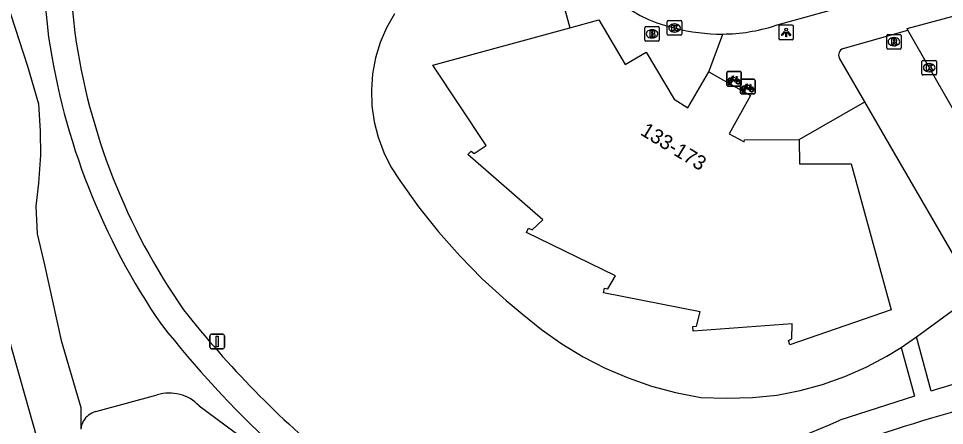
# Model space of a CAD drawing. Extents: x 159053 to 160041, y 380450 to 381422.
# Drawn here: x 159173.9 to 159237.4, y 380777.8 to 380805.8 of the extents above; entities that cross this region are included whole.
import ezdxf

# ---------------------------------------------------------------- set-up
doc = ezdxf.new("R2010")
doc.units = 0
for name, color, linetype in [('IMGEO_Brandkraan', 7, 'Continuous'), ('IMGEO_Fietsenrek', 7, 'Continuous'), ('IMGEO_Groenvoorziening', 7, 'Continuous'), ('IMGEO_Kolk', 7, 'Continuous'), ('IMGEO_Lichtpunt', 7, 'Continuous'), ('IMGEO_Pand', 7, 'Continuous'), ('IMGEO_Pand_nummerreeks', 7, 'Continuous'), ('IMGEO_Parkeervlak_open', 7, 'Continuous'), ('IMGEO_Rijbaan_lokaal_open', 7, 'Continuous'), ('IMGEO_Rioolput', 7, 'Continuous'), ('IMGEO_Verkeersbordpaal', 7, 'Continuous'), ('IMGEO_Voetpad_open', 7, 'Continuous'), ('IMGEO_Waterloop', 7, 'Continuous')]:
    doc.layers.add(name, color=color, linetype=linetype)

msp = doc.modelspace()

# ---------------------------------------------------------------- linework, layer by layer
at = {"layer": 'IMGEO_Brandkraan'}
for p, q in [((159216.878, 380804.302), (159216.878, 380805.154)), ((159216.953, 380805.228), (159217.805, 380805.228)), ((159217.366, 380805.008), (159217.391, 380805.008)), ((159217.879, 380805.154), (159217.879, 380804.302)), ((159217.805, 380804.228), (159216.953, 380804.228)), ((159217.389, 380804.448), (159217.364, 380804.448))]:
    msp.add_line(p, q, dxfattribs=at)
for points in [[(159216.878, 380804.302), (159216.878, 380805.154)], [(159216.953, 380805.228), (159217.805, 380805.228)], [(159217.226, 380804.928), (159217.226, 380804.528), (159217.439, 380804.528)], [(159217.457, 380804.928), (159217.226, 380804.928)], [(159217.405, 380804.847), (159217.351, 380804.847), (159217.351, 380804.771)], [(159217.351, 380804.771), (159217.404, 380804.771)], [(159217.879, 380805.154), (159217.879, 380804.302)], [(159217.805, 380804.228), (159216.953, 380804.228)], [(159217.413, 380804.695), (159217.351, 380804.695), (159217.351, 380804.614)], [(159217.351, 380804.614), (159217.413, 380804.614)]]:
    msp.add_lwpolyline(points, dxfattribs=at)
for centre, radius, start, end in [((159216.955, 380805.152), 0.0765, 91.55205, 178.44795), ((159216.955, 380805.152), 0.0765, 91.55205, 178.44795), ((159217.406, 380804.809), 0.0379, 267.82845, 90.93552), ((159217.461, 380804.783), 0.145, 59.4692, 91.53667), ((159217.486, 380804.83), 0.0922, 285.51372, 58.15012), ((159217.491, 380804.638), 0.105, 301.31148, 78.98903), ((159217.803, 380805.152), 0.0765, 1.55205, 88.44795), ((159217.803, 380805.152), 0.0765, 1.55205, 88.44795), ((159216.955, 380804.304), 0.0765, 181.55205, 268.44795), ((159216.955, 380804.304), 0.0765, 181.55205, 268.44795), ((159217.414, 380804.654), 0.0404, 269.87594, 90.50774), ((159217.445, 380804.779), 0.251, 268.66757, 293.53466), ((159217.803, 380804.304), 0.0765, 271.55205, 358.44795), ((159217.803, 380804.304), 0.0765, 271.55205, 358.44795)]:
    msp.add_arc(centre, radius, start, end, dxfattribs=at)
for centre, major_axis, ratio, start_param, end_param in [((159217.365, 380804.728), (-0.387, 0.002), 0.722429, 4.712389, 7.853982), ((159217.39, 380804.728), (-0.39, 0.002), 0.717154, 1.570796, 4.712389)]:
    msp.add_ellipse(centre, major_axis=major_axis, ratio=ratio, start_param=start_param, end_param=end_param, dxfattribs=at)
at = {"layer": 'IMGEO_Fietsenrek'}
for p, q in [((159222.506, 380801.224), (159222.506, 380802.065)), ((159222.506, 380802.065), (159222.506, 380801.224)), ((159222.581, 380802.149), (159223.422, 380802.149)), ((159223.422, 380802.149), (159222.581, 380802.149)), ((159223.193, 380801.698), (159223.229, 380801.603)), ((159223.506, 380802.074), (159223.506, 380801.233)), ((159223.506, 380801.233), (159223.506, 380802.074)), ((159223.524, 380801.608), (159224.365, 380801.608)), ((159224.365, 380801.608), (159223.524, 380801.608)), ((159223.431, 380801.149), (159222.59, 380801.149)), ((159222.59, 380801.149), (159223.431, 380801.149)), ((159222.633, 380801.233), (159222.672, 380801.393)), ((159222.667, 380801.233), (159222.633, 380801.233)), ((159222.702, 380801.381), (159222.667, 380801.233)), ((159222.744, 380801.405), (159222.743, 380801.409)), ((159222.785, 380801.233), (159222.751, 380801.375)), ((159222.775, 380801.416), (159222.776, 380801.409)), ((159222.783, 380801.379), (159222.818, 380801.233)), ((159222.818, 380801.233), (159222.785, 380801.233)), ((159223.449, 380800.683), (159223.449, 380801.524)), ((159223.449, 380801.524), (159223.449, 380800.683)), ((159224.136, 380801.157), (159224.172, 380801.062)), ((159224.449, 380801.533), (159224.449, 380800.692)), ((159224.449, 380800.692), (159224.449, 380801.533)), ((159224.374, 380800.608), (159223.533, 380800.608)), ((159223.533, 380800.608), (159224.374, 380800.608)), ((159223.576, 380800.692), (159223.615, 380800.852)), ((159223.61, 380800.692), (159223.576, 380800.692)), ((159223.645, 380800.84), (159223.61, 380800.692)), ((159223.687, 380800.864), (159223.686, 380800.868)), ((159223.728, 380800.692), (159223.694, 380800.834)), ((159223.718, 380800.875), (159223.719, 380800.868)), ((159223.726, 380800.838), (159223.761, 380800.692)), ((159223.761, 380800.692), (159223.728, 380800.692))]:
    msp.add_line(p, q, dxfattribs=at)
for points in [[(159222.84, 380801.623), (159222.788, 380801.533), (159222.748, 380801.508), (159222.749, 380801.555), (159222.804, 380801.649)], [(159222.819, 380801.675), (159222.914, 380801.839), (159223, 380801.825), (159223.002, 380801.816), (159222.946, 380801.805), (159222.919, 380801.76), (159223.175, 380801.719)], [(159223.115, 380801.431), (159223.065, 380801.431), (159222.874, 380801.682), (159222.855, 380801.65)], [(159223.162, 380801.694), (159222.905, 380801.735), (159222.888, 380801.706), (159223.055, 380801.486), (159223.162, 380801.694)], [(159223.21, 380801.596), (159223.18, 380801.673), (159223.071, 380801.455), (159223.114, 380801.455)], [(159223.144, 380801.455), (159223.264, 380801.454), (159223.22, 380801.568)], [(159223.24, 380801.575), (159223.295, 380801.43), (159223.145, 380801.43)], [(159223.175, 380801.719), (159223.2, 380801.768), (159223.194, 380801.772), (159223.171, 380801.776), (159223.159, 380801.783), (159223.158, 380801.786), (159223.16, 380801.791), (159223.255, 380801.776), (159223.257, 380801.766), (159223.247, 380801.753), (159223.235, 380801.747), (159223.221, 380801.753), (159223.193, 380801.698)], [(159223.783, 380801.082), (159223.731, 380800.992), (159223.691, 380800.967), (159223.692, 380801.014), (159223.747, 380801.108)], [(159223.762, 380801.134), (159223.857, 380801.298), (159223.943, 380801.284), (159223.945, 380801.275), (159223.889, 380801.264), (159223.862, 380801.219), (159224.118, 380801.178)], [(159224.058, 380800.89), (159224.008, 380800.89), (159223.817, 380801.141), (159223.798, 380801.109)], [(159224.105, 380801.153), (159223.848, 380801.194), (159223.831, 380801.165), (159223.998, 380800.945), (159224.105, 380801.153)], [(159224.153, 380801.055), (159224.123, 380801.132), (159224.014, 380800.914), (159224.057, 380800.914)], [(159224.087, 380800.914), (159224.207, 380800.913), (159224.163, 380801.027)], [(159224.183, 380801.034), (159224.238, 380800.889), (159224.088, 380800.889)], [(159224.118, 380801.178), (159224.143, 380801.227), (159224.137, 380801.231), (159224.114, 380801.235), (159224.102, 380801.242), (159224.101, 380801.245), (159224.103, 380801.25), (159224.198, 380801.235), (159224.2, 380801.225), (159224.19, 380801.212), (159224.178, 380801.206), (159224.164, 380801.212), (159224.136, 380801.157)]]:
    msp.add_lwpolyline(points, dxfattribs=at)
for centre, radius, start, end in [((159222.584, 380802.071), 0.0779, 92.4484, 184.28452), ((159222.584, 380802.071), 0.0779, 92.4484, 184.28452), ((159222.746, 380801.534), 0.159, 62.67661, 242.13685), ((159222.746, 380801.534), 0.129, 63.31916, 238.90302), ((159222.746, 380801.534), 0.129, 283.60429, 43.43025), ((159222.746, 380801.534), 0.159, 283.5766, 46.60424), ((159223.273, 380801.45), 0.159, 113.3408, 178.32165), ((159223.273, 380801.45), 0.159, 187.0065, 105.77075), ((159223.273, 380801.45), 0.129, 113.92302, 177.95563), ((159223.273, 380801.45), 0.129, 188.67146, 104.58832), ((159223.428, 380802.071), 0.0779, 2.4484, 94.28452), ((159223.428, 380802.071), 0.0779, 2.4484, 94.28452), ((159223.527, 380801.53), 0.0779, 92.4484, 184.28452), ((159223.527, 380801.53), 0.0779, 92.4484, 184.28452), ((159224.371, 380801.53), 0.0779, 2.4484, 94.28452), ((159224.371, 380801.53), 0.0779, 2.4484, 94.28452), ((159222.584, 380801.227), 0.0779, 182.4484, 274.28452), ((159222.584, 380801.227), 0.0779, 182.4484, 274.28452), ((159222.726, 380801.405), 0.0499, 12.8025, 158.69338), ((159222.746, 380801.534), 0.159, 253.99666, 271.78671), ((159222.726, 380801.405), 0.0174, 12.8025, 163.45023), ((159222.746, 380801.534), 0.129, 253.41502, 269.02044), ((159223.428, 380801.227), 0.0779, 272.4484, 4.28452), ((159223.428, 380801.227), 0.0779, 272.4484, 4.28452), ((159223.689, 380800.993), 0.159, 62.67661, 242.13685), ((159223.689, 380800.993), 0.129, 63.31916, 238.90302), ((159223.689, 380800.993), 0.129, 283.60429, 43.43025), ((159223.689, 380800.993), 0.159, 283.5766, 46.60424), ((159224.216, 380800.909), 0.159, 113.3408, 178.32165), ((159224.216, 380800.909), 0.159, 187.0065, 105.77075), ((159224.216, 380800.909), 0.129, 113.92302, 177.95563), ((159224.216, 380800.909), 0.129, 188.67146, 104.58832), ((159223.527, 380800.686), 0.0779, 182.4484, 274.28452), ((159223.527, 380800.686), 0.0779, 182.4484, 274.28452), ((159223.669, 380800.864), 0.0499, 12.8025, 158.69338), ((159223.689, 380800.993), 0.159, 253.99666, 271.78671), ((159223.669, 380800.864), 0.0174, 12.8025, 163.45023), ((159223.689, 380800.993), 0.129, 253.41502, 269.02044), ((159224.371, 380800.686), 0.0779, 272.4484, 4.28452), ((159224.371, 380800.686), 0.0779, 272.4484, 4.28452)]:
    msp.add_arc(centre, radius, start, end, dxfattribs=at)
at = {"layer": 'IMGEO_Groenvoorziening'}
for points in [[(159157.361, 380852.49), (159157.5, 380851.935), (159158.238, 380851.91), (159159.044, 380848.136), (159163.047, 380833.48), (159167.797, 380815.145), (159168.307, 380814.08), (159168.71, 380813.63), (159169.403, 380812.854), (159170.582, 380811.629), (159171.589, 380810.256), (159172.467, 380808.688), (159173.399, 380806.044), (159174.529, 380802.504), (159175.289, 380799.933), (159175.411, 380798.052), (159175.434, 380796.406), (159175.295, 380794.475), (159175.114, 380792.902), (159175.195, 380791.012), (159175.709, 380788.864), (159176.846, 380783.679), (159178.187, 380779.088), (159178.194, 380777.607)], [(159199.714, 380806.111), (159199.173, 380805.15), (159198.739, 380804.135), (159198.417, 380803.08), (159198.213, 380801.995), (159198.127, 380800.895), (159198.16, 380799.792), (159198.314, 380798.7), (159198.585, 380797.63), (159198.97, 380796.596), (159199.466, 380795.611), (159200.083, 380794.66), (159201.356, 380792.861), (159202.725, 380791.133), (159204.186, 380789.483), (159205.735, 380787.915), (159207.367, 380786.433), (159208.479, 380785.511), (159209.8, 380784.431), (159211.193, 380783.447), (159212.652, 380782.563), (159214.169, 380781.784), (159215.738, 380781.113), (159217.35, 380780.554), (159218.997, 380780.11), (159220.72, 380779.775), (159222.499, 380779.715), (159224.278, 380779.774), (159225.949, 380779.94), (159227.532, 380780.245), (159229.086, 380780.667), (159230.603, 380781.203), (159232.077, 380781.85), (159233.498, 380782.606), (159234.471, 380783.205)], [(159235.534, 380783.935), (159239.534, 380786.855)]]:
    msp.add_lwpolyline(points, dxfattribs=at)
at = {"layer": 'IMGEO_Kolk'}
for p, q in [((159218.424, 380804.709), (159218.424, 380805.561)), ((159218.499, 380805.635), (159219.351, 380805.635)), ((159218.912, 380805.415), (159218.937, 380805.415)), ((159219.425, 380805.561), (159219.425, 380804.709)), ((159218.935, 380804.855), (159218.91, 380804.855)), ((159219.351, 380804.635), (159218.499, 380804.635)), ((159235.897, 380801.98), (159235.897, 380802.832)), ((159235.972, 380802.906), (159236.824, 380802.906)), ((159236.898, 380802.832), (159236.898, 380801.98)), ((159236.385, 380802.686), (159236.41, 380802.686)), ((159236.824, 380801.906), (159235.972, 380801.906)), ((159236.408, 380802.126), (159236.383, 380802.126))]:
    msp.add_line(p, q, dxfattribs=at)
for points in [[(159218.424, 380804.709), (159218.424, 380805.561)], [(159218.499, 380805.635), (159219.351, 380805.635)], [(159219.425, 380805.561), (159219.425, 380804.709)], [(159218.745, 380805.335), (159218.868, 380805.335), (159218.868, 380805.184), (159218.998, 380805.335), (159219.162, 380805.335), (159219.016, 380805.184), (159219.169, 380804.935), (159219.017, 380804.935), (159218.932, 380805.099), (159218.868, 380805.032), (159218.868, 380804.935), (159218.745, 380804.935), (159218.745, 380805.335)], [(159219.351, 380804.635), (159218.499, 380804.635)], [(159235.897, 380801.98), (159235.897, 380802.832)], [(159235.972, 380802.906), (159236.824, 380802.906)], [(159236.898, 380802.832), (159236.898, 380801.98)], [(159236.218, 380802.606), (159236.341, 380802.606), (159236.341, 380802.455), (159236.471, 380802.606), (159236.635, 380802.606), (159236.489, 380802.455), (159236.642, 380802.206), (159236.49, 380802.206), (159236.405, 380802.37), (159236.341, 380802.303), (159236.341, 380802.206), (159236.218, 380802.206), (159236.218, 380802.606)], [(159236.824, 380801.906), (159235.972, 380801.906)]]:
    msp.add_lwpolyline(points, dxfattribs=at)
for centre, start, end in [((159218.501, 380805.559), 91.55205, 178.44795), ((159218.501, 380805.559), 91.55205, 178.44795), ((159219.349, 380805.559), 1.55205, 88.44795), ((159219.349, 380805.559), 1.55205, 88.44795), ((159218.501, 380804.711), 181.55205, 268.44795), ((159218.501, 380804.711), 181.55205, 268.44795), ((159219.349, 380804.711), 271.55205, 358.44795), ((159219.349, 380804.711), 271.55205, 358.44795), ((159235.974, 380802.83), 91.55205, 178.44795), ((159235.974, 380802.83), 91.55205, 178.44795), ((159236.822, 380802.83), 1.55205, 88.44795), ((159236.822, 380802.83), 1.55205, 88.44795), ((159235.974, 380801.982), 181.55205, 268.44795), ((159235.974, 380801.982), 181.55205, 268.44795), ((159236.822, 380801.982), 271.55205, 358.44795), ((159236.822, 380801.982), 271.55205, 358.44795)]:
    msp.add_arc(centre, 0.0765, start, end, dxfattribs=at)
for centre, major_axis, ratio, start_param, end_param in [((159218.911, 380805.135), (-0.387, 0.002), 0.722429, 4.712389, 7.853982), ((159218.936, 380805.135), (-0.39, 0.002), 0.717154, 1.570796, 4.712389), ((159236.384, 380802.406), (-0.387, 0.002), 0.722429, 4.712389, 7.853982), ((159236.409, 380802.406), (-0.39, 0.002), 0.717154, 1.570796, 4.712389)]:
    msp.add_ellipse(centre, major_axis=major_axis, ratio=ratio, start_param=start_param, end_param=end_param, dxfattribs=at)
at = {"layer": 'IMGEO_Lichtpunt'}
for p, q in [((159226.083, 380805.232), (159226.083, 380804.425)), ((159226.083, 380805.232), (159226.083, 380804.425)), ((159226.985, 380805.327), (159226.177, 380805.327)), ((159226.985, 380805.327), (159226.177, 380805.327)), ((159227.079, 380804.425), (159227.079, 380805.232)), ((159227.079, 380804.425), (159227.079, 380805.232)), ((159226.177, 380804.331), (159226.985, 380804.331)), ((159226.177, 380804.331), (159226.985, 380804.331))]:
    msp.add_line(p, q, dxfattribs=at)
for points in [[(159226.457, 380804.896), (159226.496, 380804.868), (159226.308, 380804.606), (159226.27, 380804.633), (159226.457, 380804.896)], [(159226.559, 380804.848), (159226.606, 380804.848), (159226.606, 380804.526), (159226.559, 380804.526), (159226.559, 380804.848)], [(159226.669, 380804.868), (159226.707, 380804.895), (159226.894, 380804.633), (159226.855, 380804.605), (159226.669, 380804.868)]]:
    msp.add_lwpolyline(points, dxfattribs=at)
msp.add_circle((159226.582, 380805.03), 0.0994, dxfattribs=at)
for centre, start, end in [((159226.177, 380805.232), 90, 180), ((159226.177, 380805.232), 90, 180), ((159226.985, 380805.232), 0, 90), ((159226.985, 380805.232), 0, 90), ((159226.177, 380804.425), 180, 270), ((159226.177, 380804.425), 180, 270), ((159226.985, 380804.425), 270, 0), ((159226.985, 380804.425), 270, 360)]:
    msp.add_arc(centre, 0.0946, start, end, dxfattribs=at)
at = {"layer": 'IMGEO_Pand'}
for points in [[(159211.745, 380805.145), (159213.733, 380805.694), (159215.531, 380802.628), (159216.973, 380803.467), (159218.889, 380800.241), (159219.838, 380799.655), (159221.267, 380802.133)], [(159227.479, 380797.488), (159227.498, 380795.798), (159231.043, 380795.813), (159233.78, 380785.791), (159226.843, 380783.387), (159226.748, 380783.688), (159226.977, 380783.797), (159226.987, 380784.819), (159220.196, 380784.331), (159220.178, 380784.645), (159220.435, 380784.659), (159220.677, 380785.65), (159214.062, 380786.958), (159214.118, 380787.272), (159214.355, 380787.231), (159214.864, 380788.117), (159208.762, 380791.103), (159208.905, 380791.387), (159209.165, 380791.267), (159209.891, 380791.973), (159204.744, 380796.453), (159204.968, 380796.686), (159205.181, 380796.525), (159206.007, 380797.068), (159202.339, 380802.574), (159211.745, 380805.145)], [(159221.267, 380802.133), (159224.143, 380800.501), (159222.679, 380797.864), (159223.697, 380797.317), (159223.726, 380797.455), (159227.479, 380797.488)]]:
    msp.add_lwpolyline(points, dxfattribs=at)
at = {"layer": 'IMGEO_Parkeervlak_open'}
msp.add_lwpolyline([(159238.879, 380788.148), (159234.015, 380796.548), (159231.975, 380800.065)], dxfattribs=at)
at = {"layer": 'IMGEO_Rijbaan_lokaal_open'}
for points in [[(159263.275, 380815.492), (159254.307, 380813.067), (159229.759, 380806.373), (159225.787, 380805.28)], [(159234.929, 380804.973), (159234.89, 380805.091), (159249.357, 380809.009), (159249.391, 380808.875)], [(159243.944, 380789.247), (159234.929, 380804.973)]]:
    msp.add_lwpolyline(points, dxfattribs=at)
for centre, radius, start, end in [((159220.896, 380814.173), 9.251, 195.99591, 257.67011), ((159222.105, 380816.98), 12.264, 254.95066, 270.58198), ((159222.115, 380816.943), 12.227, 270.54111, 287.47858)]:
    msp.add_arc(centre, radius, start, end, dxfattribs=at)
at = {"layer": 'IMGEO_Rioolput'}
for p, q in [((159233.478, 380803.763), (159233.478, 380804.615)), ((159233.553, 380804.689), (159234.405, 380804.689)), ((159233.966, 380804.469), (159233.991, 380804.469)), ((159234.479, 380804.615), (159234.479, 380803.763)), ((159234.405, 380803.689), (159233.553, 380803.689)), ((159233.989, 380803.909), (159233.964, 380803.909))]:
    msp.add_line(p, q, dxfattribs=at)
for points in [[(159233.478, 380803.763), (159233.478, 380804.615)], [(159233.553, 380804.689), (159234.405, 380804.689)], [(159234.067, 380804.387), (159233.815, 380804.389), (159233.815, 380803.989)], [(159233.815, 380803.989), (159233.939, 380803.989), (159233.939, 380804.151), (159233.95, 380804.151)], [(159233.993, 380804.308), (159233.939, 380804.308), (159233.939, 380804.227)], [(159233.939, 380804.227), (159233.991, 380804.227)], [(159233.997, 380804.122), (159234.068, 380803.989), (159234.208, 380803.989), (159234.143, 380804.115)], [(159234.479, 380804.615), (159234.479, 380803.763)], [(159234.405, 380803.689), (159233.553, 380803.689)]]:
    msp.add_lwpolyline(points, dxfattribs=at)
for centre, radius, start, end in [((159233.555, 380804.613), 0.0765, 91.55205, 178.44795), ((159233.555, 380804.613), 0.0765, 91.55205, 178.44795), ((159233.949, 380804.098), 0.0533, 26.02933, 88.69889), ((159233.975, 380804.416), 0.19, 274.7715, 282.96867), ((159233.999, 380804.212), 0.0964, 77.00612, 93.18647), ((159234.013, 380804.269), 0.0378, 276.66336, 79.67722), ((159234.066, 380804.277), 0.109, 350.36119, 89.41601), ((159234.064, 380804.277), 0.112, 277.58423, 350.98172), ((159234.048, 380804.062), 0.108, 29.51342, 73.79051), ((159234.403, 380804.613), 0.0765, 1.55205, 88.44795), ((159234.403, 380804.613), 0.0765, 1.55205, 88.44795), ((159233.555, 380803.765), 0.0765, 181.55205, 268.44795), ((159233.555, 380803.765), 0.0765, 181.55205, 268.44795), ((159234.403, 380803.765), 0.0765, 271.55205, 358.44795), ((159234.403, 380803.765), 0.0765, 271.55205, 358.44795)]:
    msp.add_arc(centre, radius, start, end, dxfattribs=at)
for centre, major_axis, ratio, start_param, end_param in [((159233.965, 380804.189), (-0.387, 0.002), 0.722429, 4.712389, 7.853982), ((159233.99, 380804.189), (-0.39, 0.002), 0.717154, 1.570796, 4.712389)]:
    msp.add_ellipse(centre, major_axis=major_axis, ratio=ratio, start_param=start_param, end_param=end_param, dxfattribs=at)
at = {"layer": 'IMGEO_Verkeersbordpaal'}
for p, q in [((159187.053, 380783.213), (159187.053, 380784.013)), ((159187.053, 380784.013), (159187.053, 380783.213)), ((159187.153, 380784.113), (159187.943, 380784.113)), ((159187.943, 380784.113), (159187.153, 380784.113)), ((159188.043, 380784.013), (159188.043, 380783.213)), ((159188.043, 380783.213), (159188.043, 380784.013)), ((159187.943, 380783.113), (159187.153, 380783.113)), ((159187.153, 380783.113), (159187.943, 380783.113))]:
    msp.add_line(p, q, dxfattribs=at)
msp.add_lwpolyline([(159187.473, 380783.988), (159187.623, 380783.988), (159187.623, 380783.238), (159187.473, 380783.238), (159187.473, 380783.988)], dxfattribs=at)
for centre, start, end in [((159187.153, 380784.013), 90, 180), ((159187.153, 380784.013), 90, 180), ((159187.943, 380784.013), 0, 90), ((159187.943, 380784.013), 360, 90), ((159187.153, 380783.213), 180, 270), ((159187.153, 380783.213), 180, 270), ((159187.943, 380783.213), 270, 0), ((159187.943, 380783.213), 270, 0)]:
    msp.add_arc(centre, 0.1, start, end, dxfattribs=at)
at = {"layer": 'IMGEO_Voetpad_open'}
for points in [[(159210.666, 380809.103), (159211.745, 380805.145)], [(159230.485, 380803.725), (159234.929, 380804.973)], [(159221.267, 380802.133), (159222.23, 380804.716)], [(159231.975, 380800.065), (159230.235, 380803.067)], [(159227.479, 380797.488), (159231.975, 380800.065)], [(159234.471, 380783.205), (159235.534, 380783.935)], [(159236.526, 380780.215), (159235.534, 380783.935)], [(159234.471, 380783.205), (159235.377, 380779.872), (159230.253, 380778.207)]]:
    msp.add_lwpolyline(points, dxfattribs=at)
for centre, radius, start, end in [((159483.248, 380837.004), 308.978, 179.4123, 186.0365), ((159486.162, 380836.959), 310.058, 179.41371, 185.95511), ((159221.457, 380810.983), 44.116, 188.06839, 214.81925), ((159222.142, 380811.228), 46.645, 188.27974, 214.55538), ((159230.655, 380803.284), 0.472, 111.03089, 207.36161), ((159239.772, 380828.773), 69.435, 218.24343, 230.49329), ((159239.892, 380828.9), 71.428, 218.15619, 227.20454), ((159272.049, 380660.811), 124.576, 100.1431, 106.56776), ((159274.059, 380652.272), 131.534, 99.98701, 109.13594), ((159203.263, 380838.764), 66.3, 274.22711, 294.02219)]:
    msp.add_arc(centre, radius, start, end, dxfattribs=at)
at = {"layer": 'IMGEO_Waterloop'}
for points in [[(159178.726, 380764.487), (159154.39, 380850.661), (159153.137, 380855.378), (159150.722, 380864.907), (159147.229, 380877.446), (159142.467, 380894.874), (159139.07, 380907.114), (159136.325, 380917.673)], [(159179.217, 380778.805), (159183.438, 380779.957)], [(159186.303, 380779.207), (159190.536, 380776.052), (159190.72, 380775.801), (159199.511, 380763.789)]]:
    msp.add_lwpolyline(points, dxfattribs=at)
for centre, radius, start, end in [((159184.253, 380777.223), 2.853, 44.06182, 106.59876), ((159179.582, 380777.459), 1.394, 105.16135, 151.00498), ((159179.549, 380777.466), 1.363, 150.6201, 174.07966)]:
    msp.add_arc(centre, radius, start, end, dxfattribs=at)

# ---------------------------------------------------------------- texts
at = {"layer": 'IMGEO_Pand_nummerreeks'}
msp.add_text('133-173', height=1, rotation=328.69399, dxfattribs=at).set_placement((159216.515, 380797.845))

doc.saveas('drawing.dxf')
